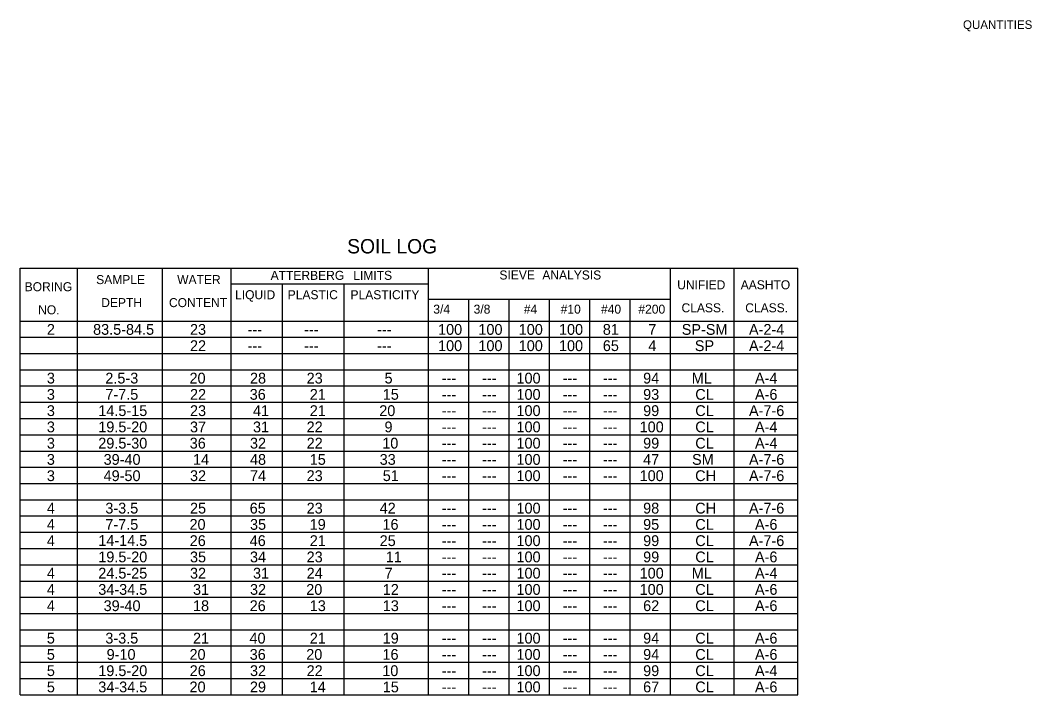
# Model space of a CAD drawing. Extents: x 1197542 to 1207464, y 185022 to 237324.
# Drawn here: x 1206911.8 to 1207052.3, y 185125.1 to 185218.9 of the extents above; entities that cross this region are included whole.
import ezdxf

# ---------------------------------------------------------------- set-up
doc = ezdxf.new("R2010")
doc.units = 0
doc.layers.add('R_Border', color=7, linetype='Continuous')
doc.layers.add('R_No Plot', color=7, linetype='Continuous')

msp = doc.modelspace()

# ---------------------------------------------------------------- linework, layer by layer
at = {"layer": 'R_No Plot'}
for p, q in [((1206911.83, 185184.42), (1206911.83, 185184.42)), ((1206911.83, 185184.42), (1207019.8, 185184.42)), ((1206911.83, 185125.12), (1206911.83, 185184.42)), ((1206919.77, 185125.12), (1206919.77, 185184.42)), ((1206931.61, 185125.12), (1206931.61, 185184.42)), ((1206941.11, 185125.12), (1206941.11, 185184.42)), ((1206968.54, 185125.12), (1206968.54, 185184.42)), ((1207002.13, 185125.12), (1207002.13, 185184.42)), ((1207010.96, 185125.12), (1207010.96, 185184.42)), ((1207019.8, 185125.12), (1207019.8, 185184.42)), ((1206941.11, 185182.25), (1206968.54, 185182.25)), ((1206948.26, 185125.12), (1206948.26, 185182.25)), ((1206956.84, 185125.12), (1206956.84, 185182.25)), ((1206968.54, 185180.09), (1207002.13, 185180.09)), ((1206974.14, 185125.12), (1206974.14, 185180.09)), ((1206979.74, 185125.12), (1206979.74, 185180.09)), ((1206985.34, 185125.12), (1206985.34, 185180.09)), ((1206990.94, 185125.12), (1206990.94, 185180.09)), ((1206996.53, 185125.12), (1206996.53, 185180.09)), ((1206911.83, 185177.07), (1207019.8, 185177.07)), ((1207002.13, 185177.07), (1207019.8, 185177.07)), ((1206911.83, 185174.81), (1207019.8, 185174.81)), ((1206911.83, 185172.55), (1207019.8, 185172.55)), ((1206911.83, 185170.29), (1207019.8, 185170.29)), ((1206911.83, 185168.04), (1207019.8, 185168.04)), ((1206911.83, 185165.78), (1207019.8, 185165.78)), ((1206911.83, 185163.52), (1207019.8, 185163.52)), ((1206911.83, 185161.26), (1207019.8, 185161.26)), ((1206911.83, 185159), (1207019.8, 185159)), ((1206911.83, 185156.74), (1207019.8, 185156.74)), ((1206911.83, 185154.48), (1207019.8, 185154.48)), ((1206911.83, 185152.22), (1207019.8, 185152.22)), ((1206911.83, 185149.97), (1207019.8, 185149.97)), ((1206911.83, 185147.71), (1207019.8, 185147.71)), ((1206911.83, 185145.45), (1207019.8, 185145.45)), ((1206911.83, 185143.19), (1207019.8, 185143.19)), ((1206911.83, 185140.93), (1207019.8, 185140.93)), ((1206911.83, 185138.67), (1207019.8, 185138.67)), ((1206911.83, 185136.41), (1207019.8, 185136.41)), ((1206911.83, 185134.15), (1207019.8, 185134.15)), ((1206911.83, 185131.9), (1207019.8, 185131.9)), ((1206911.83, 185129.64), (1207019.8, 185129.64)), ((1206911.83, 185127.38), (1207019.8, 185127.38)), ((1206911.83, 185125.12), (1207019.8, 185125.12))]:
    msp.add_line(p, q, dxfattribs=at)

# ---------------------------------------------------------------- texts
at = {"layer": 'R_Border'}
msp.add_text('QUANTITIES', height=1.2, rotation=360, dxfattribs=at).set_placement((1207042.76, 185217.66))
at = {"layer": 'R_No Plot'}
for s, height, p in [('SOIL LOG', 2, (1206957.24, 185186.46)), ('ATTERBERG', 1.25, (1206946.61, 185182.79)), ('LIMITS', 1.25, (1206958.09, 185182.79)), ('SIEVE', 1.25, (1206978.38, 185182.84)), ('ANALYSIS', 1.25, (1206984.34, 185182.84)), ('SAMPLE', 1.25, (1206922.38, 185182.2)), ('WATER', 1.25, (1206933.63, 185182.2)), ('UNIFIED', 1.25, (1207003.07, 185181.48)), ('AASHTO', 1.25, (1207011.89, 185181.48)), ('BORING', 1.25, (1206912.45, 185181.21)), ('LIQUID', 1.25, (1206941.67, 185180.1)), ('PLASTIC', 1.25, (1206948.98, 185180.1)), ('PLASTICITY', 1.25, (1206957.7, 185180.1)), ('DEPTH', 1.25, (1206923.08, 185179)), ('CONTENT', 1.25, (1206932.49, 185179)), ('NO.', 1.25, (1206914.32, 185178)), ('3/4', 1.25, (1206969.2, 185178.09)), ('3/8', 1.25, (1206974.8, 185178.09)), ('#4', 1.25, (1206981.77, 185178.09)), ('#10', 1.25, (1206986.89, 185178.09)), ('#40', 1.25, (1206992.49, 185178.09)), ('#200', 1.25, (1206997.68, 185178.09)), ('CLASS.', 1.25, (1207003.67, 185178.28)), ('CLASS.', 1.25, (1207012.52, 185178.28)), ('2', 1.5, (1206915.53, 185175.15)), ('83.5-84.5', 1.5, (1206921.95, 185175.15)), ('23', 1.5, (1206935.41, 185175.15)), ('---', 1.5, (1206943.41, 185175.15)), ('---', 1.5, (1206951.26, 185175.15)), ('---', 1.5, (1206961.4, 185175.15)), ('100', 1.5, (1206969.86, 185175.15)), ('100', 1.5, (1206975.46, 185175.15)), ('100', 1.5, (1206981.06, 185175.15)), ('100', 1.5, (1206986.65, 185175.15)), ('81', 1.5, (1206992.74, 185175.15)), ('7', 1.5, (1206999.06, 185175.15)), ('SP-SM', 1.5, (1207003.7, 185175.15)), ('A-2-4', 1.5, (1207013.04, 185175.15)), ('22', 1.5, (1206935.41, 185172.89)), ('100', 1.5, (1206969.86, 185172.89)), ('100', 1.5, (1206975.46, 185172.89)), ('100', 1.5, (1206981.06, 185172.89)), ('100', 1.5, (1206986.65, 185172.89)), ('65', 1.5, (1206992.74, 185172.89)), ('4', 1.5, (1206999.06, 185172.89)), ('SP', 1.5, (1207005.52, 185172.89)), ('A-2-4', 1.5, (1207013.04, 185172.89)), ('---', 1.5, (1206943.41, 185172.89)), ('---', 1.5, (1206951.26, 185172.89)), ('---', 1.5, (1206961.4, 185172.89)), ('3', 1.5, (1206915.53, 185168.38)), ('2.5-3', 1.5, (1206923.65, 185168.38)), ('20', 1.5, (1206935.34, 185168.38)), ('28', 1.5, (1206943.74, 185168.38)), ('23', 1.5, (1206951.61, 185168.38)), ('100', 1.5, (1206980.75, 185168.38)), ('94', 1.5, (1206998.34, 185168.38)), ('5', 1.5, (1206962.43, 185168.38)), ('---', 1.5, (1206970.37, 185168.38)), ('---', 1.5, (1206975.97, 185168.38)), ('---', 1.5, (1206987.17, 185168.38)), ('---', 1.5, (1206992.76, 185168.38)), ('ML', 1.5, (1207005.09, 185168.38)), ('A-4', 1.5, (1207013.87, 185168.38)), ('3', 1.5, (1206915.53, 185166.12)), ('7-7.5', 1.5, (1206923.65, 185166.12)), ('22', 1.5, (1206935.41, 185166.12)), ('36', 1.5, (1206943.7, 185166.12)), ('21', 1.5, (1206952.04, 185166.12)), ('15', 1.5, (1206962.18, 185166.12)), ('100', 1.5, (1206980.75, 185166.12)), ('93', 1.5, (1206998.34, 185166.12)), ('CL', 1.5, (1207005.58, 185166.12)), ('A-6', 1.5, (1207013.87, 185166.12)), ('---', 1.5, (1206970.37, 185166.12)), ('---', 1.5, (1206975.97, 185166.12)), ('---', 1.5, (1206987.17, 185166.12)), ('---', 1.5, (1206992.76, 185166.12)), ('3', 1.5, (1206915.53, 185163.86)), ('14.5-15', 1.5, (1206922.67, 185163.86)), ('23', 1.5, (1206935.41, 185163.86)), ('41', 1.5, (1206944.16, 185163.86)), ('21', 1.5, (1206952.04, 185163.86)), ('20', 1.5, (1206961.69, 185163.86)), ('---', 1.5, (1206970.37, 185163.86)), ('---', 1.5, (1206975.97, 185163.86)), ('100', 1.5, (1206980.75, 185163.86)), ('---', 1.5, (1206987.17, 185163.86)), ('---', 1.5, (1206992.76, 185163.86)), ('99', 1.5, (1206998.34, 185163.86)), ('CL', 1.5, (1207005.58, 185163.86)), ('A-7-6', 1.5, (1207013.04, 185163.86)), ('3', 1.5, (1206915.53, 185161.6)), ('19.5-20', 1.5, (1206922.67, 185161.6)), ('37', 1.5, (1206935.41, 185161.6)), ('31', 1.5, (1206944.16, 185161.6)), ('22', 1.5, (1206951.61, 185161.6)), ('9', 1.5, (1206962.42, 185161.6)), ('100', 1.5, (1206980.75, 185161.6)), ('100', 1.5, (1206997.85, 185161.6)), ('CL', 1.5, (1207005.58, 185161.6)), ('A-4', 1.5, (1207013.87, 185161.6)), ('---', 1.5, (1206970.37, 185161.6)), ('---', 1.5, (1206975.97, 185161.6)), ('---', 1.5, (1206987.17, 185161.6)), ('---', 1.5, (1206992.76, 185161.6)), ('3', 1.5, (1206915.53, 185159.34)), ('29.5-30', 1.5, (1206922.67, 185159.34)), ('36', 1.5, (1206935.37, 185159.34)), ('32', 1.5, (1206943.74, 185159.34)), ('22', 1.5, (1206951.61, 185159.34)), ('10', 1.5, (1206962.11, 185159.34)), ('100', 1.5, (1206980.75, 185159.34)), ('99', 1.5, (1206998.34, 185159.34)), ('CL', 1.5, (1207005.58, 185159.34)), ('A-4', 1.5, (1207013.87, 185159.34)), ('---', 1.5, (1206970.37, 185159.34)), ('---', 1.5, (1206975.97, 185159.34)), ('---', 1.5, (1206987.17, 185159.34)), ('---', 1.5, (1206992.76, 185159.34)), ('3', 1.5, (1206915.53, 185157.08)), ('39-40', 1.5, (1206923.41, 185157.08)), ('14', 1.5, (1206935.83, 185157.08)), ('48', 1.5, (1206943.74, 185157.08)), ('15', 1.5, (1206952.04, 185157.08)), ('33', 1.5, (1206961.75, 185157.08)), ('---', 1.5, (1206970.37, 185157.08)), ('---', 1.5, (1206975.97, 185157.08)), ('100', 1.5, (1206980.75, 185157.08)), ('---', 1.5, (1206987.17, 185157.08)), ('---', 1.5, (1206992.76, 185157.08)), ('47', 1.5, (1206998.34, 185157.08)), ('SM', 1.5, (1207005.13, 185157.08)), ('A-7-6', 1.5, (1207013.04, 185157.08)), ('3', 1.5, (1206915.53, 185154.82)), ('49-50', 1.5, (1206923.41, 185154.82)), ('32', 1.5, (1206935.41, 185154.82)), ('74', 1.5, (1206943.74, 185154.82)), ('23', 1.5, (1206951.61, 185154.82)), ('51', 1.5, (1206962.18, 185154.82)), ('100', 1.5, (1206980.75, 185154.82)), ('100', 1.5, (1206997.85, 185154.82)), ('CH', 1.5, (1207005.57, 185154.82)), ('A-7-6', 1.5, (1207013.04, 185154.82)), ('---', 1.5, (1206970.37, 185154.82)), ('---', 1.5, (1206975.97, 185154.82)), ('---', 1.5, (1206987.17, 185154.82)), ('---', 1.5, (1206992.76, 185154.82)), ('4', 1.5, (1206915.53, 185150.31)), ('3-3.5', 1.5, (1206923.65, 185150.31)), ('25', 1.5, (1206935.41, 185150.31)), ('65', 1.5, (1206943.7, 185150.31)), ('23', 1.5, (1206951.61, 185150.31)), ('42', 1.5, (1206961.75, 185150.31)), ('100', 1.5, (1206980.75, 185150.31)), ('98', 1.5, (1206998.34, 185150.31)), ('CH', 1.5, (1207005.57, 185150.31)), ('A-7-6', 1.5, (1207013.04, 185150.31)), ('---', 1.5, (1206970.37, 185150.31)), ('---', 1.5, (1206975.97, 185150.31)), ('---', 1.5, (1206987.17, 185150.31)), ('---', 1.5, (1206992.76, 185150.31)), ('4', 1.5, (1206915.53, 185148.05)), ('7-7.5', 1.5, (1206923.65, 185148.05)), ('20', 1.5, (1206935.34, 185148.05)), ('35', 1.5, (1206943.74, 185148.05)), ('19', 1.5, (1206952.03, 185148.05)), ('16', 1.5, (1206962.14, 185148.05)), ('100', 1.5, (1206980.75, 185148.05)), ('95', 1.5, (1206998.34, 185148.05)), ('CL', 1.5, (1207005.58, 185148.05)), ('A-6', 1.5, (1207013.87, 185148.05)), ('---', 1.5, (1206970.37, 185148.05)), ('---', 1.5, (1206975.97, 185148.05)), ('---', 1.5, (1206987.17, 185148.05)), ('---', 1.5, (1206992.76, 185148.05)), ('4', 1.5, (1206915.53, 185145.79)), ('14-14.5', 1.5, (1206922.67, 185145.81)), ('26', 1.5, (1206935.37, 185145.79)), ('46', 1.5, (1206943.7, 185145.79)), ('21', 1.5, (1206952.04, 185145.79)), ('25', 1.5, (1206961.75, 185145.79)), ('---', 1.5, (1206970.37, 185145.79)), ('---', 1.5, (1206975.97, 185145.79)), ('100', 1.5, (1206980.75, 185145.79)), ('---', 1.5, (1206987.17, 185145.79)), ('---', 1.5, (1206992.76, 185145.79)), ('99', 1.5, (1206998.34, 185145.79)), ('CL', 1.5, (1207005.58, 185145.79)), ('A-7-6', 1.5, (1207013.04, 185145.79)), ('19.5-20', 1.5, (1206922.67, 185143.53)), ('35', 1.5, (1206935.41, 185143.53)), ('34', 1.5, (1206943.74, 185143.53)), ('23', 1.5, (1206951.61, 185143.53)), ('11', 1.5, (1206962.6, 185143.53)), ('100', 1.5, (1206980.75, 185143.53)), ('99', 1.5, (1206998.34, 185143.53)), ('CL', 1.5, (1207005.58, 185143.53)), ('A-6', 1.5, (1207013.87, 185143.53)), ('---', 1.5, (1206970.37, 185143.53)), ('---', 1.5, (1206975.97, 185143.53)), ('---', 1.5, (1206987.17, 185143.53)), ('---', 1.5, (1206992.76, 185143.53)), ('4', 1.5, (1206915.53, 185141.27)), ('24.5-25', 1.5, (1206922.67, 185141.27)), ('32', 1.5, (1206935.41, 185141.27)), ('31', 1.5, (1206944.16, 185141.27)), ('24', 1.5, (1206951.61, 185141.27)), ('7', 1.5, (1206962.43, 185141.27)), ('---', 1.5, (1206970.37, 185141.27)), ('---', 1.5, (1206975.97, 185141.27)), ('100', 1.5, (1206980.75, 185141.27)), ('---', 1.5, (1206987.17, 185141.27)), ('---', 1.5, (1206992.76, 185141.27)), ('100', 1.5, (1206997.85, 185141.27)), ('ML', 1.5, (1207005.09, 185141.27)), ('A-4', 1.5, (1207013.87, 185141.27)), ('4', 1.5, (1206915.53, 185139.01)), ('34-34.5', 1.5, (1206922.67, 185139.01)), ('31', 1.5, (1206935.83, 185139.01)), ('32', 1.5, (1206943.74, 185139.01)), ('20', 1.5, (1206951.55, 185139.01)), ('12', 1.5, (1206962.18, 185139.01)), ('100', 1.5, (1206980.75, 185139.01)), ('100', 1.5, (1206997.85, 185139.01)), ('CL', 1.5, (1207005.58, 185139.01)), ('A-6', 1.5, (1207013.87, 185139.01)), ('---', 1.5, (1206970.37, 185139.01)), ('---', 1.5, (1206975.97, 185139.01)), ('---', 1.5, (1206987.17, 185139.01)), ('---', 1.5, (1206992.76, 185139.01)), ('4', 1.5, (1206915.53, 185136.75)), ('39-40', 1.5, (1206923.41, 185136.75)), ('18', 1.5, (1206935.83, 185136.75)), ('26', 1.5, (1206943.7, 185136.75)), ('13', 1.5, (1206952.04, 185136.75)), ('13', 1.5, (1206962.18, 185136.75)), ('100', 1.5, (1206980.75, 185136.75)), ('62', 1.5, (1206998.34, 185136.75)), ('CL', 1.5, (1207005.58, 185136.75)), ('A-6', 1.5, (1207013.87, 185136.75)), ('---', 1.5, (1206970.37, 185136.75)), ('---', 1.5, (1206975.97, 185136.75)), ('---', 1.5, (1206987.17, 185136.75)), ('---', 1.5, (1206992.76, 185136.75)), ('5', 1.5, (1206915.53, 185132.24)), ('3-3.5', 1.5, (1206923.65, 185132.24)), ('21', 1.5, (1206935.83, 185132.24)), ('40', 1.5, (1206943.67, 185132.24)), ('21', 1.5, (1206952.04, 185132.24)), ('19', 1.5, (1206962.17, 185132.24)), ('100', 1.5, (1206980.75, 185132.24)), ('94', 1.5, (1206998.34, 185132.24)), ('CL', 1.5, (1207005.58, 185132.24)), ('A-6', 1.5, (1207013.87, 185132.24)), ('---', 1.5, (1206970.37, 185132.24)), ('---', 1.5, (1206975.97, 185132.24)), ('---', 1.5, (1206987.17, 185132.24)), ('---', 1.5, (1206992.76, 185132.24)), ('5', 1.5, (1206915.53, 185129.98)), ('9-10', 1.5, (1206923.83, 185129.98)), ('20', 1.5, (1206935.34, 185129.98)), ('36', 1.5, (1206943.7, 185129.98)), ('20', 1.5, (1206951.55, 185129.98)), ('16', 1.5, (1206962.14, 185129.98)), ('---', 1.5, (1206970.37, 185129.98)), ('---', 1.5, (1206975.97, 185129.98)), ('100', 1.5, (1206980.75, 185129.98)), ('---', 1.5, (1206987.17, 185129.98)), ('---', 1.5, (1206992.76, 185129.98)), ('94', 1.5, (1206998.34, 185129.98)), ('CL', 1.5, (1207005.58, 185129.98)), ('A-6', 1.5, (1207013.87, 185129.98)), ('5', 1.5, (1206915.53, 185127.72)), ('19.5-20', 1.5, (1206922.67, 185127.72)), ('26', 1.5, (1206935.37, 185127.72)), ('32', 1.5, (1206943.74, 185127.72)), ('22', 1.5, (1206951.61, 185127.72)), ('10', 1.5, (1206962.11, 185127.72)), ('100', 1.5, (1206980.75, 185127.72)), ('99', 1.5, (1206998.34, 185127.72)), ('CL', 1.5, (1207005.58, 185127.72)), ('A-4', 1.5, (1207013.87, 185127.72)), ('---', 1.5, (1206970.37, 185127.72)), ('---', 1.5, (1206975.97, 185127.72)), ('---', 1.5, (1206987.17, 185127.72)), ('---', 1.5, (1206992.76, 185127.72)), ('5', 1.5, (1206915.53, 185125.46)), ('34-34.5', 1.5, (1206922.67, 185125.46)), ('20', 1.5, (1206935.34, 185125.46)), ('29', 1.5, (1206943.73, 185125.46)), ('14', 1.5, (1206952.04, 185125.46)), ('15', 1.5, (1206962.18, 185125.46)), ('100', 1.5, (1206980.75, 185125.46)), ('67', 1.5, (1206998.34, 185125.46)), ('CL', 1.5, (1207005.58, 185125.46)), ('A-6', 1.5, (1207013.87, 185125.46)), ('---', 1.5, (1206970.37, 185125.46)), ('---', 1.5, (1206975.97, 185125.46)), ('---', 1.5, (1206987.17, 185125.46)), ('---', 1.5, (1206992.76, 185125.46))]:
    msp.add_text(s, height=height, dxfattribs=at).set_placement(p)

doc.saveas('drawing.dxf')
